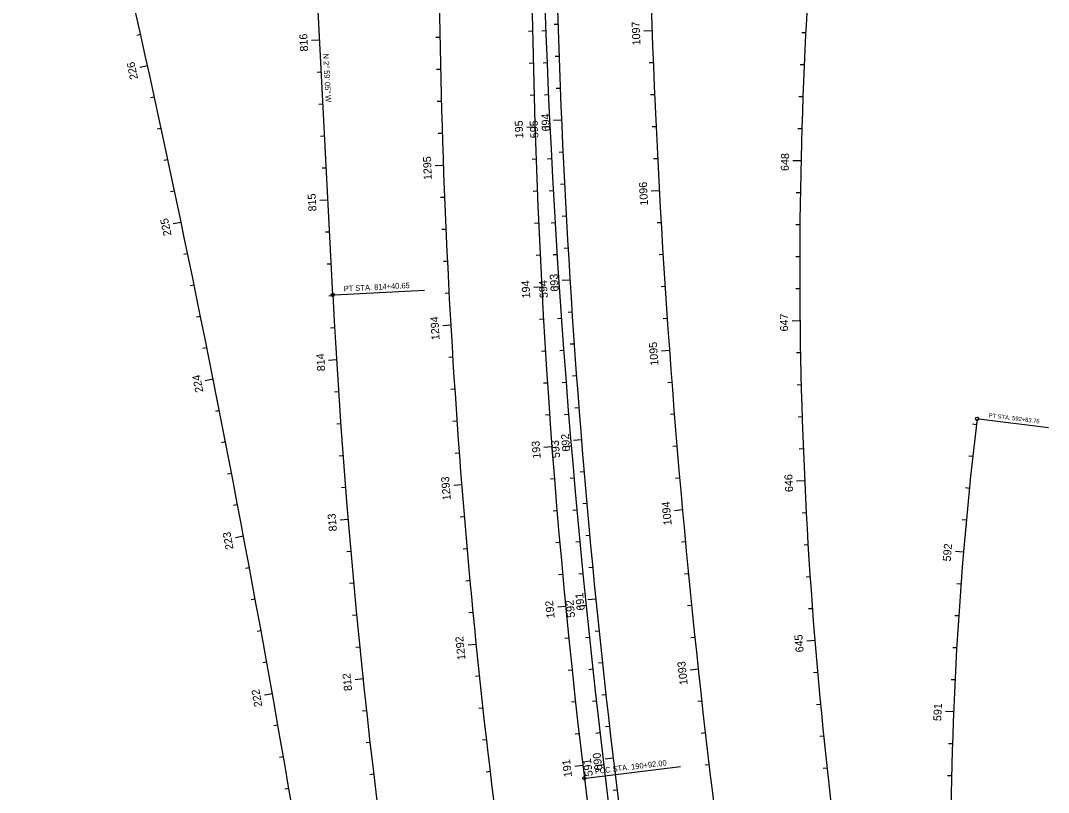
# Model space of a CAD drawing. Extents: x 919452 to 931278, y 583254 to 665650.
# Drawn here: x 928661 to 929303, y 634933 to 635415 of the extents above; entities that cross this region are included whole.
import ezdxf

# ---------------------------------------------------------------- set-up
doc = ezdxf.new("R2010")
doc.units = 0
for name, color, linetype in [('CLConst_dp', 7, 'Continuous'), ('CurveDataLabel_dp', 7, 'Continuous'), ('StationTicL_dp', 7, 'Continuous'), ('StationTicS_dp', 7, 'Continuous'), ('TextBLStation', 7, 'Continuous'), ('TextLabel', 7, 'Continuous')]:
    doc.layers.add(name, color=color, linetype=linetype)

msp = doc.modelspace()

# ---------------------------------------------------------------- linework, layer by layer
at = {"layer": 'CLConst_dp'}
msp.add_line((928856.53, 635243.73), (928842.76, 635507.87), dxfattribs=at)
for centre, radius, start, end in [((934714.76, 635630.15), 5729.58, 175.955434, 198.89818), ((919023.27, 633253.37), 9949, 9.590734, 14.358327), ((934757.45, 635620.79), 5705.58, 180.06217, 188.19915), ((934313.46, 635582.15), 5319.04, 180.05369, 188.30596), ((932014.36, 635260.36), 2866.29, 174.76849, 187.10964), ((933567.21, 635491.59), 4644.7, 180.06217, 187.81416), ((933567.17, 635491.59), 4586.66, 180.05369, 186.8847), ((933433.97, 635482.4), 4583.66, 182.98469, 189.59073), ((931534.4, 634892.3), 2292, 173.13281, 187.58667), ((934714.76, 635630.15), 5742.58, 186.884702, 191.983164)]:
    msp.add_arc(centre, radius, start, end, dxfattribs=at)
at = {"layer": 'CurveDataLabel_dp'}
for p, q in [((928857.53, 635243.78), (928913.68, 635246.71)), ((929259.84, 635166.23), (929303.41, 635160.98)), ((929014.58, 634941.9), (929073.69, 634949.04))]:
    msp.add_line(p, q, dxfattribs=at)
for centre in [(928856.53, 635243.73), (929258.84, 635166.35), (929013.58, 634941.78)]:
    msp.add_circle(centre, 1, dxfattribs=at)
at = {"layer": 'StationTicL_dp'}
for p, q in [((929055.81, 635408.73), (929050.82, 635408.54)), ((928848.23, 635402.86), (928843.24, 635402.6)), ((928740.82, 635386.86), (928735.94, 635385.79)), ((928999.37, 635352.82), (928994.38, 635352.61)), ((928982.75, 635348.48), (928977.75, 635348.32)), ((928992.09, 635348.71), (928987.1, 635348.47)), ((929148.86, 635327.49), (929143.86, 635327.61)), ((928925.51, 635324.65), (928920.52, 635324.47)), ((929060.41, 635308.83), (929055.41, 635308.56)), ((928853.44, 635303), (928848.44, 635302.74)), ((928761.77, 635289.08), (928756.88, 635288.06)), ((929004.62, 635252.96), (928999.63, 635252.65)), ((928986.95, 635248.57), (928981.96, 635248.3)), ((928997.88, 635248.88), (928992.89, 635248.55)), ((928930.18, 635224.76), (928925.19, 635224.47)), ((929148.26, 635227.5), (929143.26, 635227.44)), ((929066.75, 635209.04), (929061.76, 635208.67)), ((928858.82, 635203.14), (928853.83, 635202.84)), ((928781.74, 635191.09), (928776.84, 635190.12)), ((928993.34, 635148.78), (928988.36, 635148.4)), ((929005.4, 635149.17), (929000.42, 635148.75)), ((929011.75, 635153.22), (929006.77, 635152.81)), ((928937, 635124.99), (928932.02, 635124.6)), ((929151.15, 635127.55), (929146.16, 635127.32)), ((929074.84, 635109.36), (929069.86, 635108.92)), ((928866.01, 635103.4), (928861.02, 635102.99)), ((928800.73, 635092.91), (928795.81, 635091.99)), ((929250.35, 635083.02), (929245.37, 635083.44)), ((929020.75, 635053.63), (929015.78, 635053.13)), ((929001.9, 635049.14), (928996.93, 635048.66)), ((929014.67, 635049.6), (929009.69, 635049.09)), ((928945.97, 635025.4), (928940.99, 635024.9)), ((929157.53, 635027.76), (929152.54, 635027.35)), ((929084.68, 635009.85), (929079.7, 635009.31)), ((928875.36, 635003.84), (928870.39, 635003.32)), ((928818.72, 634994.55), (928813.8, 634993.67)), ((929244.2, 634983.22), (929239.21, 634983.42)), ((929012.63, 634949.72), (929007.67, 634949.13)), ((929025.67, 634950.21), (929020.7, 634949.61)), ((929031.62, 634954.22), (929026.66, 634953.63))]:
    msp.add_line(p, q, dxfattribs=at)
at = {"layer": 'StationTicS_dp'}
for p, q in [((928997.12, 635412.78), (928994.63, 635412.7)), ((928736.51, 635406.39), (928734.07, 635405.85)), ((928923.33, 635404.62), (928920.83, 635404.57)), ((928981.27, 635408.46), (928978.77, 635408.42)), ((928989.46, 635408.66), (928986.96, 635408.56)), ((929151.85, 635407.44), (929149.35, 635407.56)), ((928997.8, 635392.79), (928995.3, 635392.7)), ((928981.67, 635388.46), (928979.17, 635388.41)), ((928990.27, 635388.67), (928987.77, 635388.57)), ((929056.59, 635388.74), (929054.1, 635388.64)), ((929150.89, 635387.46), (929148.4, 635387.57)), ((928849.27, 635382.89), (928846.78, 635382.76)), ((928923.74, 635384.62), (928921.24, 635384.57)), ((928998.55, 635372.81), (928996.05, 635372.71)), ((928745.09, 635367.32), (928742.65, 635366.79)), ((928982.16, 635368.47), (928979.67, 635368.4)), ((928991.15, 635368.69), (928988.65, 635368.58)), ((929057.44, 635368.76), (929054.94, 635368.65)), ((929150.08, 635367.48), (929147.58, 635367.57)), ((928850.31, 635362.92), (928847.82, 635362.79)), ((928924.25, 635364.63), (928921.75, 635364.56)), ((928749.32, 635347.77), (928746.88, 635347.25)), ((929058.36, 635348.78), (929055.86, 635348.66)), ((929149.4, 635347.49), (929146.9, 635347.56)), ((928851.36, 635342.94), (928848.86, 635342.81)), ((928924.84, 635344.64), (928922.34, 635344.56)), ((928753.51, 635328.22), (928751.07, 635327.7)), ((928983.41, 635328.49), (928980.91, 635328.4)), ((928993.11, 635328.74), (928990.61, 635328.61)), ((929000.27, 635332.84), (928997.78, 635332.73)), ((929059.35, 635328.8), (929056.85, 635328.68)), ((928852.4, 635322.97), (928849.9, 635322.84)), ((928757.66, 635308.65), (928755.22, 635308.14)), ((928984.17, 635308.5), (928981.67, 635308.4)), ((928994.2, 635308.77), (928991.7, 635308.63)), ((929001.25, 635312.87), (928998.75, 635312.74)), ((928926.28, 635304.66), (928923.78, 635304.56)), ((929148.46, 635307.5), (929145.96, 635307.54)), ((928985.01, 635288.52), (928982.51, 635288.41)), ((928995.35, 635288.8), (928992.86, 635288.65)), ((929002.3, 635292.89), (928999.8, 635292.76)), ((929061.54, 635288.86), (929059.04, 635288.72)), ((928854.48, 635283.02), (928851.98, 635282.89)), ((928927.12, 635284.68), (928924.63, 635284.57)), ((929148.2, 635287.5), (929145.7, 635287.52)), ((928765.85, 635269.5), (928763.4, 635268.99)), ((929003.42, 635272.93), (929000.93, 635272.78)), ((928855.52, 635263.05), (928853.02, 635262.92)), ((928928.06, 635264.7), (928925.56, 635264.58)), ((928985.94, 635268.54), (928983.44, 635268.42)), ((928996.58, 635268.84), (928994.09, 635268.68)), ((929062.73, 635268.9), (929060.24, 635268.75)), ((929148.08, 635267.5), (929145.58, 635267.51)), ((928769.88, 635249.91), (928767.43, 635249.41)), ((928929.08, 635244.73), (928926.58, 635244.6)), ((929064, 635248.94), (929061.51, 635248.78)), ((929148.1, 635247.5), (929145.6, 635247.49)), ((928856.56, 635243.08), (928854.07, 635242.95)), ((929005.9, 635233), (929003.4, 635232.84)), ((928773.87, 635230.31), (928771.42, 635229.82)), ((928988.06, 635228.6), (928985.56, 635228.46)), ((928999.24, 635228.93), (928996.75, 635228.75)), ((929065.34, 635228.99), (929062.85, 635228.81)), ((928857.65, 635223.11), (928855.15, 635222.97)), ((929007.25, 635213.05), (929004.76, 635212.88)), ((928777.83, 635210.71), (928775.38, 635210.22)), ((928989.25, 635208.64), (928986.75, 635208.48)), ((929000.68, 635208.98), (928998.18, 635208.8)), ((929148.56, 635207.5), (929146.06, 635207.46)), ((928931.38, 635204.8), (928928.88, 635204.64)), ((929008.68, 635193.1), (929006.18, 635192.92)), ((928990.53, 635188.68), (928988.03, 635188.51)), ((929002.18, 635189.04), (928999.69, 635188.85)), ((929068.23, 635189.09), (929065.74, 635188.9)), ((929149, 635187.51), (929146.5, 635187.44)), ((928860.09, 635183.18), (928857.59, 635183.02)), ((928932.65, 635184.84), (928930.16, 635184.67)), ((929010.18, 635173.16), (929007.68, 635172.96)), ((928785.62, 635171.47), (928783.17, 635170.99)), ((928991.89, 635168.72), (928989.4, 635168.55)), ((929003.76, 635169.1), (929001.27, 635168.9)), ((929069.78, 635169.15), (929067.28, 635168.95)), ((929149.58, 635167.52), (929147.08, 635167.44)), ((928861.44, 635163.23), (928858.94, 635163.05)), ((928934.02, 635164.88), (928931.52, 635164.71)), ((929258.4, 635162.61), (929255.91, 635162.91)), ((928789.45, 635151.84), (928787, 635151.37)), ((929071.39, 635149.22), (929068.9, 635149.01)), ((929150.3, 635147.53), (929147.8, 635147.43)), ((928862.87, 635143.28), (928860.38, 635143.09)), ((928935.47, 635144.94), (928932.97, 635144.75)), ((929256.12, 635142.74), (929253.64, 635143.02)), ((928793.25, 635132.21), (928790.8, 635131.74)), ((928994.88, 635128.84), (928992.39, 635128.64)), ((929007.12, 635129.24), (929004.63, 635129.02)), ((929013.4, 635133.29), (929010.91, 635133.08)), ((929073.08, 635129.29), (929070.59, 635129.07)), ((928864.4, 635123.34), (928861.9, 635123.14)), ((929254.02, 635122.85), (929251.54, 635123.1)), ((928797.01, 635112.56), (928794.55, 635112.1)), ((928996.5, 635108.9), (928994.01, 635108.69)), ((929008.9, 635109.32), (929006.41, 635109.09)), ((929015.13, 635113.36), (929012.64, 635113.14)), ((928938.62, 635105.06), (928936.13, 635104.85)), ((929152.15, 635107.57), (929149.65, 635107.44)), ((929252.1, 635102.95), (929249.61, 635103.18)), ((929016.93, 635093.44), (929014.44, 635093.21)), ((928867.7, 635083.47), (928865.21, 635083.26)), ((928940.33, 635085.13), (928937.84, 635084.92)), ((928998.22, 635088.97), (928995.73, 635088.76)), ((929010.75, 635089.41), (929008.26, 635089.17)), ((929076.67, 635089.45), (929074.18, 635089.22)), ((929153.28, 635087.61), (929150.79, 635087.45)), ((928804.4, 635073.25), (928801.95, 635072.8)), ((929018.8, 635073.53), (929016.31, 635073.29)), ((928942.12, 635065.21), (928939.63, 635064.98)), ((929000.02, 635069.06), (928997.53, 635068.83)), ((929012.67, 635069.5), (929010.19, 635069.25)), ((929078.56, 635069.54), (929076.08, 635069.3)), ((929154.56, 635067.65), (929152.07, 635067.48)), ((928869.49, 635063.55), (928867, 635063.33)), ((929248.77, 635063.09), (929246.28, 635063.27)), ((928808.04, 635053.59), (928805.58, 635053.14)), ((928944, 635045.3), (928941.51, 635045.06)), ((929080.53, 635049.64), (929078.04, 635049.38)), ((929155.97, 635047.7), (929153.48, 635047.51)), ((928871.36, 635043.64), (928868.87, 635043.4)), ((929247.37, 635043.13), (929244.87, 635043.3)), ((928811.64, 635033.91), (928809.18, 635033.47)), ((929022.78, 635033.73), (929020.29, 635033.47)), ((929003.87, 635029.24), (929001.39, 635028.99)), ((929016.73, 635029.71), (929014.24, 635029.44)), ((929082.57, 635029.74), (929080.08, 635029.48)), ((928873.32, 635023.74), (928870.83, 635023.49)), ((929246.14, 635023.17), (929243.64, 635023.32)), ((928815.2, 635014.23), (928812.74, 635013.79)), ((929024.88, 635013.84), (929022.39, 635013.57)), ((929005.93, 635009.35), (929003.45, 635009.09)), ((929018.86, 635009.82), (929016.37, 635009.55)), ((929159.22, 635007.83), (929156.73, 635007.61)), ((928948.02, 635005.51), (928945.53, 635005.24)), ((929245.08, 635003.2), (929242.59, 635003.32)), ((929027.05, 634993.96), (929024.57, 634993.68)), ((929008.08, 634989.46), (929005.6, 634989.19)), ((929021.06, 634989.94), (929018.57, 634989.66)), ((929086.85, 634989.97), (929084.37, 634989.69)), ((929161.05, 634987.91), (929158.56, 634987.67)), ((928877.49, 634983.96), (928875.01, 634983.69)), ((928950.15, 634985.62), (928947.67, 634985.35)), ((928822.2, 634974.85), (928819.74, 634974.42)), ((929029.3, 634974.08), (929026.82, 634973.8)), ((929010.31, 634969.59), (929007.83, 634969.3)), ((929023.33, 634970.07), (929020.84, 634969.78)), ((929089.1, 634970.1), (929086.61, 634969.81)), ((929163.02, 634968.01), (929160.54, 634967.75)), ((928879.71, 634964.08), (928877.23, 634963.8)), ((928952.38, 634965.74), (928949.89, 634965.46)), ((929243.5, 634963.23), (929241, 634963.31)), ((928825.64, 634955.15), (928823.18, 634954.72)), ((929091.41, 634950.23), (929088.93, 634949.94)), ((928882.01, 634944.21), (928879.53, 634943.92)), ((928954.68, 634945.88), (928952.2, 634945.58)), ((929165.13, 634948.12), (929162.65, 634947.85)), ((929242.97, 634943.24), (929240.47, 634943.3)), ((928829.04, 634935.44), (928826.58, 634935.02)), ((929034.02, 634934.36), (929031.54, 634934.06))]:
    msp.add_line(p, q, dxfattribs=at)

# ---------------------------------------------------------------- texts
at = {"layer": 'CurveDataLabel_dp'}
for s, height, rotation, p in [('PT STA. 814+40.65', 3.5, 2.98469, (928863.43, 635245.84)), ('PT STA. 592+83.76', 2.625, 353.13281, (929266, 635167.25)), ('PCC STA. 190+92.00', 3.5, 6.8847, (929020.32, 634944.36))]:
    msp.add_text(s, height=height, rotation=rotation, dxfattribs=at).set_placement(p)
at = {"layer": 'TextBLStation'}
for s, rotation, p in [('1097', 92.13005, (929048.64, 635399.74)), ('816', 92.98469, (928841.08, 635395.95)), ('226', 102.38281, (928734.9, 635378.87)), ('694', 92.47107, (928992.16, 635346.02)), ('195', 91.78802, (928975.45, 635341.68)), ('595', 92.81552, (928984.93, 635341.79)), ('1295', 92.05982, (928918.33, 635315.58)), ('648', 88.6579, (929141.21, 635321.1)), ('1096', 93.13425, (929053.4, 635299.66)), ('815', 92.98469, (928846.29, 635296.05)), ('225', 101.80691, (928755.78, 635281.12)), ('693', 93.54825, (928997.55, 635245.92)), ('194', 93.0372, (928979.81, 635241.69)), ('594', 93.81552, (928990.83, 635241.91)), ('647', 90.65685, (929140.84, 635220.94)), ('1294', 93.2934, (928923.2, 635215.61)), ('1095', 94.13846, (929059.9, 635199.71)), ('814', 93.49286, (928851.73, 635196.21)), ('224', 101.23102, (928775.65, 635183.27)), ('692', 94.62543, (929004.81, 635146.05)), ('193', 94.28638, (928986.35, 635141.64)), ('593', 94.81552, (928998.48, 635141.97)), ('1293', 94.52697, (928930.22, 635115.6)), ('646', 92.65581, (929143.96, 635120.67)), ('1094', 95.14266, (929068.15, 635100)), ('813', 94.74286, (928859.08, 635096.22)), ('223', 100.65512, (928794.57, 635085.05)), ('592', 85.22675, (929242.33, 635077.08)), ('691', 95.70262, (929013.9, 635046.77)), ('192', 95.53556, (928995.07, 635041.87)), ('592', 95.81552, (929007.87, 635042.29)), ('1292', 95.76054, (928939.39, 635015.86)), ('645', 94.65476, (929150.59, 635020.6)), ('1093', 96.14687, (929078.16, 635000.26)), ('812', 95.99286, (928868.59, 634996.51)), ('222', 100.07923, (928812.49, 634986.75)), ('591', 87.72657, (929236.47, 634977.39)), ('690', 96.7798, (929024.95, 634946.86)), ('191', 96.78475, (929005.91, 634942.75)), ('591', 96.81552, (929018.95, 634943.22))]:
    msp.add_text(s, height=5, rotation=rotation, dxfattribs=at).set_placement(p)
at = {"layer": 'TextLabel'}
msp.add_text('N 2%%d 59\' 05" W', height=3.5, rotation=272.98469, dxfattribs=at).set_placement((928850.42, 635394.49))

doc.saveas('drawing.dxf')
